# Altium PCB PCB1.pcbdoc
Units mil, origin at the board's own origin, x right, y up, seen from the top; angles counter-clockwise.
Board outline 3685 x 2990 mil, 2 copper layers (Top Layer, Bottom Layer); 23 components, 20 nets, 80 pads, 476 vias.
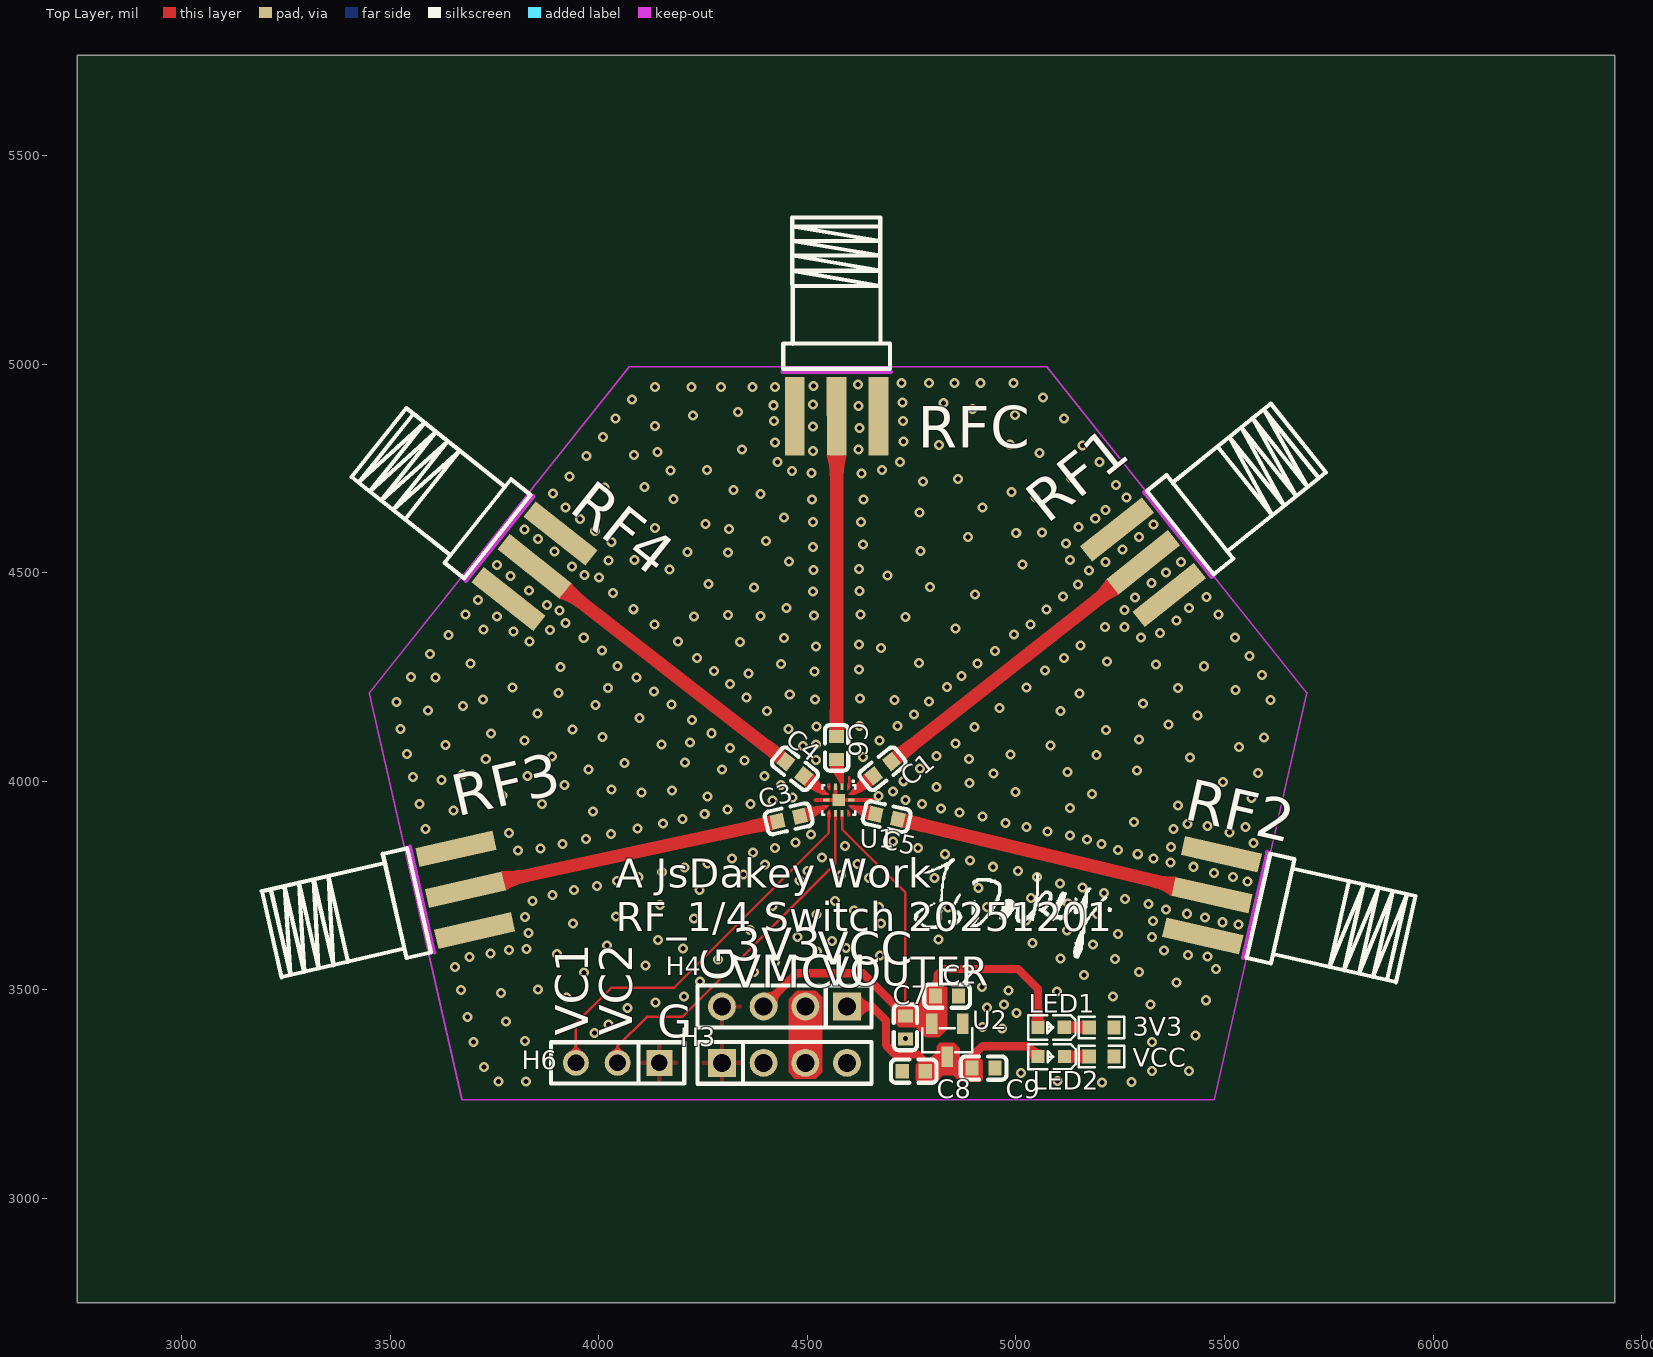
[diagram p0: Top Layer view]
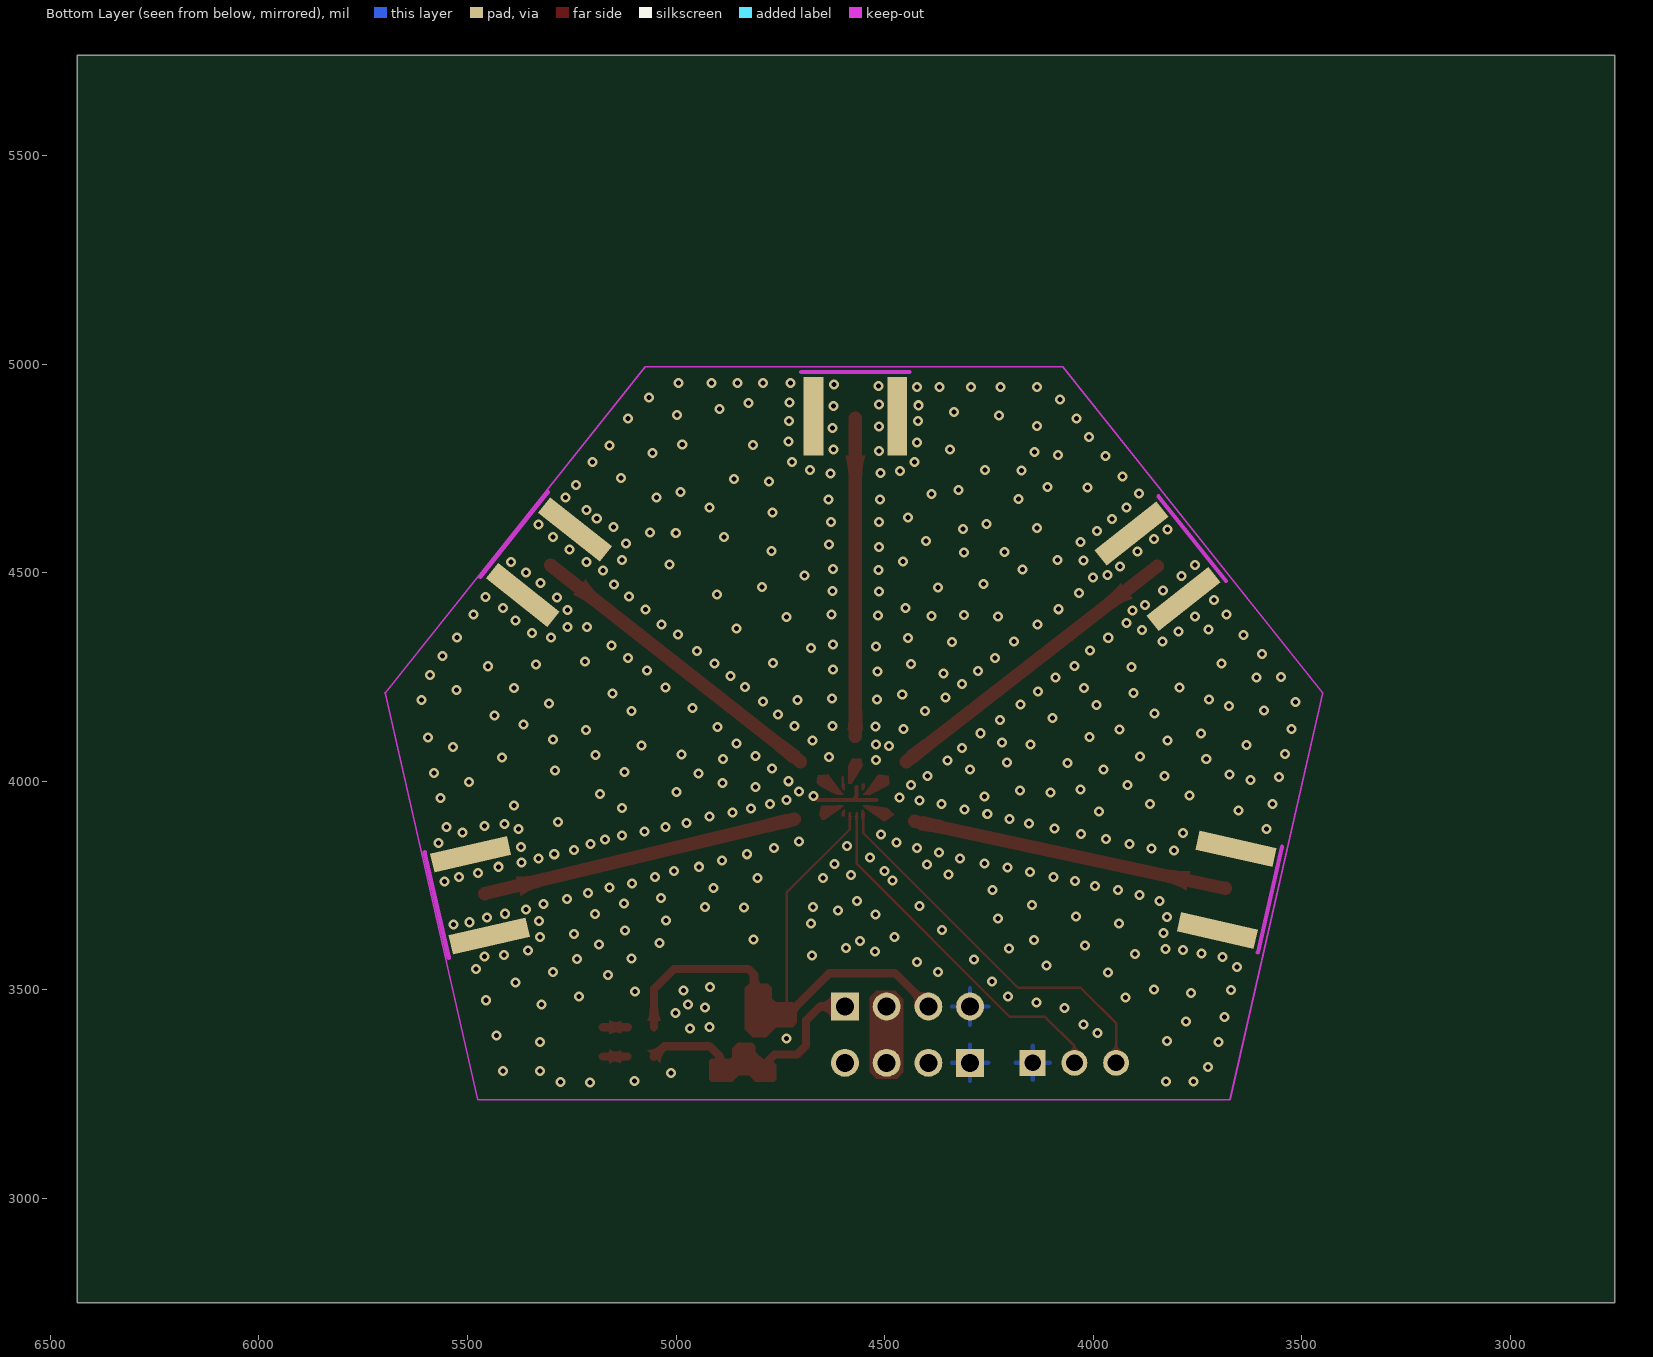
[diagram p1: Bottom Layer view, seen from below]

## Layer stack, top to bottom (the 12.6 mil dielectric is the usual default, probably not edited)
Top Layer: signal copper (thickness not stored)
Dielectric: dielectric 12.6, FR-4, Dk 4.8
Bottom Layer: signal copper (thickness not stored)

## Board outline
6435,2750 2750,2750 2750,5740 6435,5740

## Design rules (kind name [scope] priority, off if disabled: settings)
BoardOutlineClearance copperThickness1oz [All] p0: genericclearance=10 ignorepadtopadclearanceinfootprint=FALSE except(0: Arc-SplitContinuation Track-SplitContinuation SMDPad-SplitContinuation THPad-SplitContinuation Via-SplitContinuation Fill-SplitContinuation Poly-SplitContinuation Region-SplitContinuation Text-SplitContinuation; 6: Track-CutoutEdge SMDPad-CutoutEdge THPad-CutoutEdge Via-CutoutEdge Region-CutoutEdge; 11.8: Track-OutlineEdge SMDPad-OutlineEdge THPad-OutlineEdge Via-OutlineEdge Fill-OutlineEdge Region-OutlineEdge Poly-OutlineEdge Text-OutlineEdge Fill-CutoutEdge)
BoardOutlineClearance copperThickness2oz [All] p0: genericclearance=10 ignorepadtopadclearanceinfootprint=FALSE except(0: Arc-SplitContinuation Track-SplitContinuation SMDPad-SplitContinuation THPad-SplitContinuation Via-SplitContinuation Fill-SplitContinuation Poly-SplitContinuation Region-SplitContinuation Text-SplitContinuation; 6: Track-CutoutEdge SMDPad-CutoutEdge THPad-CutoutEdge Via-CutoutEdge Region-CutoutEdge; 11.8: Track-OutlineEdge SMDPad-OutlineEdge THPad-OutlineEdge Via-OutlineEdge Fill-OutlineEdge Region-OutlineEdge Poly-OutlineEdge Text-OutlineEdge Fill-CutoutEdge)
Clearance copperThickness1oz [(InNet('$1N1095') OR InNet('$1N976') OR InNet('3V3') OR InNet('GND') OR InNet('$1N986') OR InNet('$1N962') OR InNet('$1N936') OR InNet('$1N951') OR InNet('$1N981') OR InNet('$1N970') OR InNet('VCC') OR InNet('VMCU') OR InNet('$1N2051') OR InNet('VOUTER') OR InNet('VC1') OR InNet('VC2') OR InNet('$1N1695') OR InNet('$1N1711') OR InNet('$1N2530') OR InNet('$1N2570'))] p1: gap=7 ignorepadtopadclearanceinfootprint=FALSE except(4: Track-Track; 6: Track-SMDPad SMDPad-SMDPad Track-THPad SMDPad-THPad THPad-THPad Track-Via SMDPad-Via THPad-Via Via-Via Track-Fill SMDPad-Fill THPad-Fill Via-Fill Fill-Fill Track-Region SMDPad-Region THPad-Region Via-Region Region-Region Track-Poly SMDPad-Poly THPad-Poly Via-Poly Fill-Poly Region-Poly Poly-Poly Track-Text SMDPad-Text THPad-Text Via-Text Fill-Text Region-Text Poly-Text Text-Text; 6.9: Track-Hole SMDPad-Hole THPad-Hole Via-Hole Fill-Hole Region-Hole Poly-Hole Text-Hole Sheet-Hole; 11.8: Fill-Region Track-Sheet SMDPad-Sheet THPad-Sheet Via-Sheet Fill-Sheet Region-Sheet Poly-Sheet Text-Sheet)
Clearance copperThickness2oz [All] p1: gap=7 ignorepadtopadclearanceinfootprint=FALSE except(6: Track-SMDPad SMDPad-SMDPad Track-THPad SMDPad-THPad THPad-THPad Track-Via SMDPad-Via THPad-Via Via-Via SMDPad-Fill THPad-Fill Via-Fill Fill-Fill Track-Region SMDPad-Region THPad-Region Via-Region Region-Region Track-Poly SMDPad-Poly THPad-Poly Via-Poly Fill-Poly Region-Poly Poly-Poly Track-Text SMDPad-Text THPad-Text Via-Text Fill-Text Region-Text Poly-Text Text-Text; 6.9: Track-Hole SMDPad-Hole THPad-Hole Via-Hole Fill-Hole Region-Hole Poly-Hole Text-Hole Sheet-Hole; 8: Track-Track; 11.8: Track-Fill Fill-Region Track-Sheet SMDPad-Sheet THPad-Sheet Via-Sheet Fill-Sheet Region-Sheet Poly-Sheet Text-Sheet)
DiffPairsRouting differentialPair [All] p1: maxuncoupledlength=10 minlimit=6 maxlimit=6 mostfreqgap=6 toplayer_minwidth=5 toplayer_prefwidth=10 toplayer_maxwidth=100 bottomlayer_minwidth=5 bottomlayer_prefwidth=10 bottomlayer_maxwidth=100
PasteMaskExpansion pasteMaskExpansion [All] p1: expansion=0
PlaneConnect innerPlane [All] p1: planeconnectstyle=Relief reliefexpansion=20 reliefentries=4 reliefconductorwidth=10 reliefairgap=10
PolygonConnect copperRegion [All] p1: connectstyle=Direct reliefentries=4 reliefconductorwidth=10 polygonreliefangle="90 Angle" airgapwidth=10
RoutingVias viaSize [All] p1: viastyle="Through Hole" holewidth=12.0078 minholewidth=11.811 maxholewidth=248.0314 width=24.0158 minwidth=19.685 maxwidth=393.7008
SolderMaskExpansion solderMaskExpansion [All] p1: useseparateexpansions=TRUE expansion=2 expansionbottom=2
Width copperThickness1oz [All] p1: maxlimit=100 minlimit=5 preferedwidth=10
Width copperThickness2oz [All] p1: maxlimit=100 minlimit=8 preferedwidth=10

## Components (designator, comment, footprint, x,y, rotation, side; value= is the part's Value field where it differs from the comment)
3V3 "Res_0603" R0603 5205,3410 r0 top
C1 "CAP_0603" C0603 4680,4030 r38.58 top
C2 "CAP_0603" C0603 4834.88,3485 r180 top
C3 "CAP_0603" C0603 4455,3910 r12.87 top
C4 "CAP_0603" C0603 4470,4030 r321.43 top
C5 "CAP_0603" C0603 4690,3915 r347.15 top
C6 "CAP_0603" C0603 4570,4080 r270 top
C7 "CAP_0603" C0603 4735,3410 r90 top
C8 "CAP_0603" C0603 4755,3305 r0 top
C9 "CAP_0603" C0603 4922.44,3312.56 r180 top
H3 "HDR-F_2.54_1x4P" HDR-TH_4P-P2.54-V-F 4445,3325 r0 top
H4 "HDR-F_2.54_1x4P" HDR-TH_4P-P2.54-V-F 4445,3460 r180 top
H6 "HDR-F_2.54_1x3P" HDR-TH_3P-P2.54-V-F 4045,3325 r180 top
LED1 "LED_0603-R" LED_0603 5082.63,3339.58 r180 top
LED2 "LED_0603-R" LED_0603 5082.1,3409.8 r180 top
RF1 "BWSMA-KE-P001" SMA-SMD_BWSMA-KE-P001 5305,4525 r38.62 top
RF2 "BWSMA-KE-P001" SMA-SMD_BWSMA-KE-P001 5470,3726.92 r347.17 top
RF3 "BWSMA-KE-P001" SMA-SMD_BWSMA-KE-P001 3680,3740 r192.87 top
RF4 "BWSMA-KE-P001" SMA-SMD_BWSMA-KE-P001 3845.77,4515.38 r141.44 top
RFC "BWSMA-KE-P001" SMA-SMD_BWSMA-KE-P001 4570,4875 r90.04 top
U1 "SKY13575-639LF" QFN-14_L1.6-W1.6-P0.40-BL-EP0.7 4575,3955 r180 top
U2 "662K" SOT-23-3_L2.9-W1.3-P1.90-LS2.4-BR 4835,3378.74 r90 top
VCC "Res_0603" R0603 5205,3340 r0 top

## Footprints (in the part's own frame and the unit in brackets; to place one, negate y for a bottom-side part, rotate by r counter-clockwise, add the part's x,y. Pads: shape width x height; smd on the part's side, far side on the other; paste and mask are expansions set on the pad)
C0603 [mm]
  rect 0.8x0.9 smd: 1(-0.7,0) 2(0.7,0)
  silkscreen extent -1.39,-0.71 1.39,0.71
HDR-TH_3P-P2.54-V-F [mil]
  rect 62x62 hole 40.16: 1(-100,0)
  round 62 hole 40.16: 2(0,0) 3(100,0)
  silkscreen extent -160,-49 160,49
HDR-TH_4P-P2.54-V-F [mm]
  rect 1.7x1.7 hole 1.1: 1(-3.81,0)
  round 1.7 hole 1.1: 2(-1.27,0) 3(1.27,0) 4(3.81,0)
  silkscreen extent -5.29,-1.27 5.29,1.27
LED_0603 [mil]
  rect 31.5x31.5 smd: 1(-33.5,-0.4) 2(29.5,-0.2)
  silkscreen extent -61,-30 53,30
QFN-14_L1.6-W1.6-P0.40-BL-EP0.7 [mm]
  round 0.038 smd: 1(-0.606,-0.788) 4(0.596,-0.788) 5(0.792,-0.4) 7(0.782,0.4) 8(0.595,0.788) 11(-0.606,0.788) 12(-0.792,0.4) 14(-0.788,-0.408)
  rect 0.2x0.4 smd: 2(-0.205,-0.8) 3(0.195,-0.8) 9(0.195,0.8) 10(-0.205,0.8)
  rect 0.4x0.2 smd: 6(0.767,0) 13(-0.777,0)
  rect 0.74x0.74 smd: 15(-0.005,0)
  Top Layer region: 0.595,0.306 0.594,0.386 0.735,0.495 0.97,0.496 0.97,0.304
  Top Layer region: -0.605,0.306 -0.605,0.386 -0.745,0.495 -0.98,0.496 -0.98,0.304
  Top Layer region: -0.601,-0.313 -0.6,-0.393 -0.741,-0.503 -0.976,-0.503 -0.976,-0.312
  Top Layer region: 0.605,-0.306 0.605,-0.386 0.745,-0.495 0.98,-0.496 0.98,-0.304
  Top Layer region: 0.502,-0.601 0.582,-0.6 0.691,-0.74 0.692,-0.976 0.5,-0.975
  Top Layer region: -0.512,0.601 -0.592,0.6 -0.701,0.741 -0.702,0.976 -0.51,0.976
  Top Layer region: 0.501,0.601 0.581,0.6 0.69,0.741 0.691,0.976 0.499,0.976
  Top Layer region: -0.512,-0.6 -0.592,-0.6 -0.701,-0.741 -0.702,-0.976 -0.51,-0.975
  silkscreen extent -1.02,-1.18 1.01,0.89
R0603 [mil]
  rect 31.75x34.02 smd: 1(-29.66,0) 2(29.66,0)
  silkscreen extent -55,-26 55,26
SMA-SMD_BWSMA-KE-P001 [mm]
  rect 4.8x1.2 smd: 1(0,-2.55) 2(0,2.55) 5(0,0)
  rect 4.8x1.2 smd far side: 3(0,2.55) 4(0,-2.55)
  Board Outline Layer lines w0.254: 2.7,3.3 2.7,-3.3 2.7,3.3
  silkscreen extent 2.89,-3.25 12.1,3.25
SOT-23-3_L2.9-W1.3-P1.90-LS2.4-BR [mm]
  rect 1.25x0.7 smd: 1(1,-0.95) 2(1,0.95) 3(-1,0)
  silkscreen extent -0.73,-1.53 0.73,1.53

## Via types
v1: diameter 24.02, hole 12.01, Top Layer to Bottom Layer, 476 vias

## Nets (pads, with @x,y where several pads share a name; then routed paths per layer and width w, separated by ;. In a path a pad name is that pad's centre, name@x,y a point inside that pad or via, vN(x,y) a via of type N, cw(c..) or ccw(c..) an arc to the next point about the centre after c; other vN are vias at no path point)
3V3: C2.2 C7.2 H4.3 LED2.2 U1.10 U2.2 | length 1375.6
  Top Layer w6: U1.10 4583.07,3885 4735,3733.07 C7.2
  Top Layer w20: H4.3 4475,3540 4632.56,3540 C7.2 ; C2.2 4812.8,3490.48 4812.8,3536.36 4826.44,3550 5005,3550 5052.6,3502.4 LED2.2
$1N936: C4.1 RF4.5 | length 762.4
  Top Layer w32.09: RF4.5@3846.73,4515.35 C4.1
$1N951: C5.2 RF2.5 | length 762.4
  Top Layer w32.09: C5.2 RF2.5@5458.08,3730.36
$1N962: C4.2 U1.5
$1N970: C6.2 U1.2
$1N976: C1.1 U1.14
$1N981: C5.1 U1.12
$1N986: C3.1 RF3.5 | length 762.4
  Top Layer w32.09: RF3.5@3682.83,3743.29 C3.1
$1N1095: C1.2 RF1.5 | length 762.4
  Top Layer w32.1: C1.2 RF1.5@5300.97,4518.3
$1N1695: LED1.1 VCC.1 | length 59.2
  Top Layer w20: LED1.1 VCC.1
$1N1711: 3V3.1 LED2.1 | length 59.8
  Top Layer w20: LED2.1 5175.14,3410.2 3V3.1
$1N2051: H3.3 H4.2
$1N2530: C3.2 U1.7
$1N2570: C6.1 RFC.5 | length 762.4
  Top Layer w32.09: C6.1 RFC.5@4570,4870.01
GND: 3V3.2 C2.1 C7.1 C8.1 C9.1 H3.1 H4.4 H6.1 RF1.1 RF1.2 RF1.3 RF1.4 RF2.1 RF2.2 RF2.3 RF2.4 RF3.1 RF3.2 RF3.3 RF3.4 RF4.1 RF4.2 RF4.3 RF4.4 RFC.1 RFC.2 RFC.3 RFC.4 U1.1 U1.3 U1.4 U1.6 U1.11 U1.13 U1.15 U2.1 VCC.2 | length 213.4
  Top Layer w6: U1.1 4600,3987.16 4600,4010
  Top Layer w10: 4520,3955 U1.6 U1.15 ; U1.3 4567.32,3962.86 U1.15 ; v1(4670,3965) 4659.99,3954.99 U1.13 U1.15
  other v1: 5206.4,3277.27 5277.33,3279 3760,3280 3825.55,3280 5099.14,3281.59 5011.78,3300.62 5326.57,3305 5415,3305 3725,3315 3700,3375 5326.45,3374.62 3822.65,3377.75 4735.38,3383.27 5430,3390 3989.87,3396.5 4966.8,3407.02 4919.23,3410.48 4023.22,3416.96 3777.24,3424.46 3685,3435 5001.4,3444.21 4069.06,3455.89 4930.47,3457.18 4971.13,3464.97 5322.52,3464.68 4135.67,3469.73 5455,3475 3922.56,3481.55 4204,3483.57 5233,3484.14 3765.57,3491.93 5098.71,3495.82 4982.37,3498.7 3670,3500 3853.79,3501.01 4918.36,3506.49 5384.8,3517.23 4242.06,3519.9 5162.93,3536.04 3964.08,3541.23 4372.24,3542.82 5295.27,3542.53 5480,3550 3655,3555 4111.99,3558.1 4422.84,3566.17 4286.17,3572.66 5236.89,3573.67 5107.14,3575.61 3690.49,3578.48 5459.53,3579.46 4674.55,3581.74 5412.25,3582.92 3899.2,3585.34 3740.08,3587.13 4522.74,3592.12 5354.58,3593.88 3785.06,3595.49 3826.87,3598.08 4201.51,3599.62 4592.81,3599.91 4019.87,3606.1 5184.34,3608.7 5039.67,3611.94 4559.07,3616.8 4141.83,3619.08 4813.73,3620.57 4476.03,3627.15 5325.75,3626.75 5245,3634 3830.9,3635.86 5122.06,3641.78 4362.29,3643.59 5533.58,3656.21 3938.13,3659.3 4676.03,3659.21 5495.14,3661.97 5328.06,3664.81 5023.46,3666.44 4228.22,3670.98 5453.62,3673.51 3823.12,3674.78 4040.63,3676.17 4521.45,3680.89 5194.4,3682.01 5409.8,3682.35 4612.08,3690.7 5359.44,3692.73 4672.14,3697.97 4836.81,3697.65 4930.5,3698.19 4416.78,3700.68 4147.02,3703.41 5317.92,3705.41 5124.33,3706.66 3840.42,3712.84 4565.94,3713.16 5261.79,3718.1 5036.11,3719.63 3888.86,3727.54 5211.04,3731.55 3940.76,3738.79 4240.82,3739.55 4910.25,3744.28 5160,3745 3995.25,3749.17 5105,3755 5555,3760 4043.69,3761.28 4480.9,3762 4647.11,3767.82 4805.16,3767.64 5050,3770 5520,3770 4094.72,3770.79 4580,3775 4346.26,3776.8 5475,3780 4151.81,3782.04 4499.82,3784.58 5005,3785 4205.44,3793.28 4945,3795 5425,3795 4398.73,3800.72 4619.67,3802.12 4259.93,3802.8 5370,3805 4890,3810 4318.75,3814.91 5330,3815 4535.29,3817.45 4830,3825 5291.88,3825 4369.78,3828.74 3806.4,3834.22 5245,3835 3860.6,3838.26 4422.55,3839.99 4765,3840 5371.88,3841.84 4590,3845 3913.08,3849.22 5205,3850 5569.1,3851.64 4471.85,3852.96 4705,3855 5170,3860 3969.59,3861.33 5130,3870 4028.98,3873.43 4508.18,3872.86 3784.48,3876.32 5511.43,3877.59 5075,3880 3585,3885 5377.07,3885.09 4092.42,3887.27 5025,3890 5550,3890 5458.96,3892.58 5411.67,3897.77 4153.54,3898.81 4975,3900 5283.45,3902 4200.25,3909.19 4920,3915 4253.88,3921.87 4865,3925 3985.81,3927.33 3651.06,3929.93 4308.08,3932.25 4820,3935 5129.06,3935.73 5388.55,3942.22 3570,3945 3863.85,3945.5 4364.02,3944.94 4775,3945 4415.92,3954.17 4734.96,3954.59 5565,3960 4463.78,3961.09 4260.66,3963.2 3768.7,3966.26 5182.25,3969.47 4102.58,3973.18 4705,3975 4999.31,3974.66 4175.24,3977.5 4029.92,3980.1 4809.88,3986.33 3917.48,3990.48 4436.29,3990.88 4889.02,3995.42 5496.24,3998.01 4730,4000 3622.52,4002.59 3555,4010 3829.25,4012.97 4397.46,4012.98 3673.55,4016.43 4946.11,4018.77 5580,4020 5123.87,4022.66 5289.94,4025.26 3975.43,4027.67 4295.47,4028.54 4770,4030 4061.93,4044.11 4206.38,4044.97 4349.02,4049.89 4520.05,4051.33 3728.91,4052.76 4887.73,4053.8 5417.09,4056.4 4633.58,4057.87 3887.2,4058.81 4810,4060 5192.63,4062.88 4986.33,4064.18 3540,4065 4313.85,4079.88 5535.16,4082.35 4489.49,4084.78 3632.9,4086.49 5082.35,4086.24 4150.16,4088.22 4520.63,4087.66 4855,4090 4218.49,4093.41 4672.79,4097.46 3822.33,4097.73 5295.13,4100.51 5595,4105 4009.16,4105.52 3741.02,4114.17 4270.6,4115.05 5215.99,4122.57 3525,4125 3936.51,4124.55 4454.31,4125.72 4900,4130 4521.78,4131.49 4624.69,4132.62 4715.85,4132.64 5365.19,4135.54 4223.31,4147.34 4097.39,4151.36 5435.26,4157.6 4755.06,4160.32 3853.47,4162.61 4403.57,4168.39 5107,4167.98 3590.52,4169.53 4960,4175 3674.42,4179.91 3991.86,4182.5 4173.72,4183.67 5304.21,4186.14 3515,4190 4791.96,4190.88 3721.99,4195.48 4517.74,4195.49 4708.68,4195.22 5610,4195 4625.84,4198.74 4354.55,4200.68 4457.65,4207.59 5152.41,4210.79 3903.64,4211.91 4132.2,4214.81 5526.08,4218.58 4022.14,4223.16 5388.55,4223.77 3792.92,4224.89 4834.06,4225.48 5025,4225 4314.76,4233.55 3608.68,4248.24 4090.69,4248.83 3550,4250 4869.81,4252.01 5590,4255 4358.4,4258.19 4517.17,4263.54 4275.55,4264.69 5070,4265 4623.92,4268.32 3907.96,4274.19 4044.55,4275.94 5450.83,4275.67 5335.35,4279.56 3692.58,4281.97 4436.25,4281.54 4767.06,4283.45 4907.87,4282.57 5218.58,4287.34 4235.76,4295.25 5115,4295 5560,4300 3595,4305 4007.65,4312.84 4949.97,4312.55 4676.24,4319.78 4520.05,4323.51 5155,4325 4623.92,4328.29 4338.94,4334.09 3833.5,4334.76 4189.63,4335.04 3963.82,4343.98 4444.03,4343.82 5300,4345 5525,4345 3640,4350 4994.95,4352.34 5345,4355 3795.44,4358.97 3882.51,4362.43 3723.72,4364.15 4855.29,4366.49 5213.08,4369.97 5260,4369.97 5034.73,4375.41 4133.69,4375.99 3920,4379.73 5385,4385 4228,4394.42 4734.63,4393.74 3755.65,4394.73 4387.59,4396.37 4516.01,4396.75 4309.74,4398.31 4626.8,4399.22 3680,4400 5485,4400 3905.85,4408.8 5260,4410 4083.53,4412.31 5073.37,4411.74 5415,4415 4449.87,4415.83 3875.35,4422.76 3710,4435 5285,4440 5113.16,4442.3 5456.14,4442.19 4902,4448.23 4033.93,4451.53 4513.71,4454.99 4625.07,4456.31 3833.07,4456.98 4372.02,4464.48 4794.31,4465.1 4263.03,4472.27 5148.33,4471.71 5325,4475 3999.91,4488.43 3787.96,4491.58 3965.31,4494.27 4691.81,4493.64 5360,4500 5175,4505 4169.62,4507.3 4514.28,4506.89 4623.92,4509.36 3935.26,4514.58 3756.18,4517.98 5016.18,4519.59 5215,4525 5395,4525 4455.71,4526.76 4022.69,4529.54 5130,4530 4085.93,4530.66 4309.74,4548.17 4212.43,4550.12 3893.74,4550.72 4770.96,4552.03 5255,4555 4513.13,4561.67 4633.72,4567.03 5120,4570 4030.47,4573.66 4401.21,4575.42 3853.95,4580.32 5295,4585 4885.13,4585.76 5000.61,4594.84 5062.88,4596.14 3990.68,4599.61 3821.66,4603.96 4311.69,4604.61 4134.59,4606.56 5150,4610 5330,4615 4255.25,4616.29 4628.53,4621.23 4513.13,4621.64 3954.36,4628.15 5190,4630 4444.03,4631.86 4768.36,4644.15 5215,4650 3920.62,4655.83 4920.16,4655.82 4634.3,4674.86 4511.4,4675.84 4179.35,4676.62 5047.32,4680.48 5265,4680 4387.59,4688.3 3890,4690 4988.93,4693.45 4323.37,4698.03 4013.92,4703.87 4109.29,4705.81 5240,4710 4776.58,4718.54 4860.48,4724.59 5131.65,4727.18 3930,4730 4629.11,4738.29 4510.25,4738.7 4463.54,4743.31 4171.56,4744.74 4679.28,4746.36 4259.14,4746.68 4427.79,4765.22 4721.37,4765.39 5200,4765 3970,4780 4083.98,4781.71 5056.4,4786.87 4140.42,4789.5 4513.2,4791.34 4342.83,4795.34 4622.77,4795.38 5160,4805 4815.07,4806.33 4985.04,4807.63 4422.02,4811.93 4730.02,4814.41 4010,4825 4624.5,4846.7 4513.2,4850.16 4134.59,4851.78 4419.71,4863.26 4728.87,4863.42 4040,4870 5115,4870 4226.06,4877.08 4998.01,4877.69 4333.1,4884.86 4895.51,4891.96 4622.77,4899.18 4419.14,4901.31 4513.2,4902.64 4826.75,4906.23 4728.29,4907.83 4080,4915 5065,4920 4135,4945 4222,4945 4292.92,4945 4368.18,4945 4422.67,4945 4514.93,4947.04 4621.61,4951.07 4725,4955 4791.15,4955 4852.56,4955 4914.84,4955 4994.42,4955
VC1: H6.3 U1.8 | length 938.1
  Top Layer w6: H6.3 3945,3420 4030,3505 4180,3505 4551.56,3876.56 U1.8
VC2: H6.2 U1.9 | length 864.6
  Top Layer w6: H6.2 4045,3365 4115,3435 4200,3435 4567.32,3802.32 U1.9
VCC: C8.2 C9.2 H4.1 LED1.2 U2.3 | length 506.1
  Top Layer w20: H4.1 4655,3460 4688.21,3426.79 4688.21,3366.79 4710,3345 4764.29,3345 4780,3329.29 4780,3307.56 C8.2 ; C9.2 4894.88,3339.88 4920,3365 5027.91,3365 LED1.2
VMCU: H3.2
VOUTER: H3.4

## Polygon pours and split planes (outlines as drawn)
GND on Top Layer (solid, pour order 0): 3050,5405 6100,5405 6100,3075 3050,3075
GND on Bottom Layer (solid, remove dead copper, pour order 2): 3000,5490 6185,5490 6185,3000 3000,3000

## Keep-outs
Board Outline Layer:
  lines w3.9: 3449.43,4211.53 3672,3236.61 5475.06,3236.63
  lines w3.94: 3449.43,4211.53 4072.9,4993.38 ; 4073.92,4993.38 5073.92,4993.38 5697.46,4211.58 5475.06,3236.63

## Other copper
Top Layer:
  region net $1N970: 4579.13,3994.37 4552.36,4036.76 4556.34,4054.43 4577.02,4055.14 4587.62,4036.78 4587,3994.37
  region net $1N976: 4604.16,3974.79 4635.23,4016.81 4660.12,4014.52 4663.08,3997.62 4657.17,3989.41 4625.43,3972.92 4613.42,3967.27
  region net $1N981: 4613.59,3943.02 4651.8,3941.8 4657.22,3919.22 4650.31,3907.93 4643.94,3907.41 4604.34,3935.5
  region net $1N2530: 4546.06,3935.52 4501.07,3902.46 4476.33,3919.83 4493.24,3936.83 4536.81,3943.04
  region net $1N962: 4545.66,3974.5 4514.74,4016.84 4489.55,4013.37 4488.36,3993.89 4492.8,3989.35 4536.41,3966.98
  region net 3V3: 4710.02,3437.56 4710.02,3420.51 4720.53,3410 4760,3410 4783.79,3386.21 4816.21,3386.21 4834.88,3404.88 4834.88,3505.12 4825,3515 4780,3515 4770,3505 4770,3480 4760,3470 4720,3470 4710,3460 4710,3437.58
  region net VCC: 4790,3331.8 4810,3351.8 4810,3365 4817.8,3372.8 4852.2,3372.8 4865,3360 4865,3340 4870,3335 4915,3335 4920,3330 4920,3285 4915,3280 4865,3280 4850,3295 4825,3295 4810,3280 4765,3280 4760,3285 4760,3320 4771.8,3331.8
  region net $1N2051: 4475,3497.31 4520,3497.31 4535,3482.31 4535,3302.31 4520,3287.31 4470,3287.31 4455,3302.31 4455,3477.31
  region net $1N1095: 4741.76,4099.21 4761.8,4074.13 ccw(c5223.79,3486.32) 4724.9,4043.16 4702.81,4070.86 ccw(c4338.78,4611.94)
  region net 3V3: 4802.8,3532.72 4822.8,3532.72 ccw(c6483.31,3532.7) 4823.07,3502.72 4791.57,3502.72 ccw(c4757.1,3532.72)
  region net $1N986: 4369.28,3874.77 4362.09,3906.05 ccw(c4196.46,4674.86) 4408.83,3917.62 4416.73,3883.08 ccw(c4500.24,3266.88)
  region net $1N936: 4388.01,4073.88 4408.05,4098.94 ccw(c4791.37,4591.61) 4447.19,4070.85 4425.09,4043.15 ccw(c3907.46,3456.23)
  region net $1N951: 4782.52,3909.56 4775.43,3878.26 ccw(c4592,3116.66) 4728.28,3888.1 4736.16,3922.64 ccw(c4928.56,4515.94)
  region net $1N2570: 4553.95,4171.44 4586.05,4171.44 ccw(c5279.97,4171.44) 4587.72,4123.31 4552.28,4123.31 ccw(c3860.03,4171.44)
  region net 3V3: 4732,3462.31 4738,3462.31 ccw(c4749.25,3462.31) 4742.5,3453.31 4727.5,3453.31 ccw(c4720.75,3462.31)
  region net 3V3: 4705.73,3452.69 4721.84,3464.86 ccw(c4752.72,3500.34) 4752.72,3453.31 4717.28,3421.81 ccw(c4670.25,3421.81)
  region net VCC: 4770,3329.29 4790,3329.29 ccw(c4798.31,3331.25) 4798.31,3322.72 4766.81,3322.72 ccw(c4761.62,3329.29)
  region net VCC: 4884.88,3339.88 4904.88,3339.88 ccw(c4915.78,3339.88) 4910.63,3330.28 4879.13,3330.28 ccw(c4873.98,3339.88)
  region net VCC: 4655,3470 4655,3450 ccw(c4655,3419.03) 4628.46,3435 4628.46,3485 ccw(c4655,3500.97)
  region net 3V3: 4420.14,3499.29 4434.29,3485.14 4432.9,3483.63 4431.75,3482.12 4430.81,3480.61 4430.06,3479.09 4429.49,3477.54 4429.07,3475.98 4428.58,3472.77 4428.45,3469.4 4428.49,3465.83 4428.53,3462.01 4428.4,3457.9 4392.9,3493.4 4397.01,3493.53 4400.83,3493.49 4404.4,3493.45 4407.77,3493.58 4410.98,3494.07 4412.54,3494.49 4414.09,3495.06 4415.61,3495.81 4417.12,3496.75 4418.63,3497.9
  region net VC1: 3942,3367.2 3948,3367.2 3948.17,3365.76 3948.66,3364.31 3949.43,3362.85 3950.45,3361.39 3953.07,3358.49 3956.23,3355.64 3962.95,3350.24 3965.93,3347.77 3968.25,3345.5 3921.75,3345.5 3924.07,3347.77 3927.05,3350.24 3933.77,3355.64 3936.93,3358.49 3939.55,3361.39 3940.57,3362.85 3941.34,3364.31 3941.83,3365.76
  region net VC2: 4042,3365 4048,3365 4048.17,3363.58 4048.66,3362.2 4049.43,3360.85 4050.45,3359.53 4053.07,3356.98 4056.23,3354.53 4062.95,3349.9 4065.93,3347.68 4068.25,3345.5 4021.75,3345.5 4024.07,3347.68 4027.05,3349.9 4033.77,3354.53 4036.93,3356.98 4039.55,3359.53 4040.57,3360.85 4041.34,3362.2 4041.83,3363.58
  region net $1N1695: 5161.88,3349.98 5161.88,3329.98 ccw(c5161.88,3248.84) 5131.88,3324.23 5131.88,3355.73 ccw(c5161.88,3431.11)
  region net VCC: 5024.85,3353.92 5038.99,3368.06 ccw(c5069.25,3398.33) 5068.88,3355.53 5037.38,3324.03 ccw(c4994.58,3323.66)
  region net $1N1711: 5161.35,3420.2 5161.35,3400.2 ccw(c5161.35,3319.06) 5131.35,3394.45 5131.35,3425.95 ccw(c5161.35,3501.34)
  region net 3V3: 5042.6,3455.75 5062.6,3455.75 ccw(c5143.74,3455.75) 5068.35,3425.75 5036.85,3425.75 ccw(c4961.46,3455.75)
  region net $1N1695: 5129.46,3329.98 5129.46,3349.98 ccw(c5129.46,3417.5) 5159.46,3357.01 5159.46,3322.99 ccw(c5129.46,3262.07)
  region net $1N1711: 5129.46,3400.2 5129.46,3420.2 ccw(c5129.46,3489.7) 5159.46,3427.01 5159.46,3392.99 ccw(c5129.46,3334.17)
  region net $1N936: 3968.74,4440.75 3948.6,4415.76 ccw(c3868.9,4313.33) 3904.92,4438.01 3934.37,4474.96 ccw(c4091.24,4598.19)
  region net $1N2570: 4586.05,4732.4 4553.95,4732.36 ccw(c4396.06,4732.36) 4546.44,4780.5 4593.68,4780.53 ccw(c4741.54,4732.4)
  region net $1N951: 5328.01,3745.18 5334.95,3776.52 ccw(c5381.92,3971.53) 5383.12,3770.94 5372.63,3724.88 ccw(c5297.72,3619.42)
  region net $1N1095: 5204.64,4422.18 5184.51,4447.18 ccw(c5106.94,4545.88) 5216.43,4484.49 5245.92,4447.58 ccw(c5335.63,4255.51)
  region net $1N986: 3815.19,3788.22 3822.53,3756.98 ccw(c3850.5,3627.15) 3777.37,3738.01 3766.85,3784.07 ccw(c3774.69,3976.25)
  region net VC1: 4554.56,3907.59 4548.56,3907.58 ccw(c4495.1,3907.58) 4547.8,3916.58 4548.56,3916.58 4554.56,3916.59 4555.35,3916.59 ccw(c4606.54,3907.59)
  region net 3V3: 4586.07,3906.63 4580.07,3906.63 ccw(c4536.38,3906.63) 4579.13,3915.63 4587.01,3915.63 ccw(c4629.76,3906.63)
  region net VC2: 4570.32,3906.63 4564.32,3906.63 ccw(c4520.63,3906.63) 4563.38,3915.63 4571.26,3915.63 ccw(c4614.01,3906.63)

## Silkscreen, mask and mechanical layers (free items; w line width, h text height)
Top Silkscreen Layer:
  drawing of 7 lines, arcs and shapes, not listed
  text "A JsDakey Work / RF_1/4 Switch 20251201" at 4040,3640 h70
  text "3V3" at 4320,3570 h80
  text "VCC" at 4525,3560 h80
  text "G" at 4325,3520 h80 r90
  text "VOUTER" at 4535,3510 h70
  text "VMCU" at 4315,3505 h80
  text "VC1" at 3975,3390 h80 r90
  text "VC2" at 4080,3390 h80 r90
  text "G" at 4140,3385 h80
